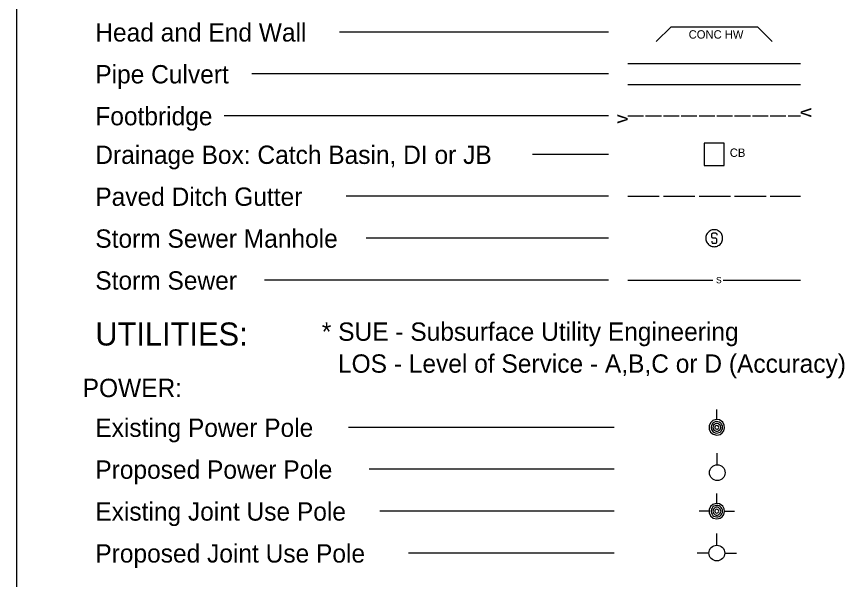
# Model space of a CAD drawing. Extents: x 754056.72 to 754059.56, y 596603.78 to 596605.61.
# Drawn here: x 754058.141 to 754058.806, y 596604.7 to 596605.152 of the extents above; entities that cross this region are included whole.
import ezdxf

# ---------------------------------------------------------------- set-up
doc = ezdxf.new("R2010")
doc.units = 0
doc.layers.add('Sheet_Symbology', color=7, linetype='Continuous')
doc.layers.add('z - Construction', color=7, linetype='Continuous')

msp = doc.modelspace()

# ---------------------------------------------------------------- linework, layer by layer
at = {"layer": 'Sheet_Symbology'}
for p, q in [((754058.65501, 596605.13174), (754058.66691, 596605.14364)), ((754058.66691, 596605.14364), (754058.73627, 596605.14364)), ((754058.73627, 596605.14364), (754058.74817, 596605.13174)), ((754058.61659, 596605.13943), (754058.40084, 596605.13943)), ((754058.63222, 596605.11421), (754058.77095, 596605.11421)), ((754058.61659, 596605.1058), (754058.3304, 596605.1058)), ((754058.63222, 596605.09739), (754058.77095, 596605.09739)), ((754058.61659, 596605.07217), (754058.30806, 596605.07217)), ((754058.63222, 596605.07217), (754058.64484, 596605.07217)), ((754058.64652, 596605.07217), (754058.65913, 596605.07217)), ((754058.66081, 596605.07217), (754058.67342, 596605.07217)), ((754058.6751, 596605.07217), (754058.68772, 596605.07217)), ((754058.6894, 596605.07217), (754058.70201, 596605.07217)), ((754058.70369, 596605.07217), (754058.7163, 596605.07217)), ((754058.71798, 596605.07217), (754058.7306, 596605.07217)), ((754058.73228, 596605.07217), (754058.74489, 596605.07217)), ((754058.74657, 596605.07217), (754058.75918, 596605.07217)), ((754058.76086, 596605.07217), (754058.77095, 596605.07217)), ((754058.61659, 596605.04117), (754058.55556, 596605.04117)), ((754058.61659, 596605.00754), (754058.40608, 596605.00754)), ((754058.63222, 596605.00754), (754058.65745, 596605.00754)), ((754058.66081, 596605.00754), (754058.68603, 596605.00754)), ((754058.6894, 596605.00754), (754058.71462, 596605.00754)), ((754058.71798, 596605.00754), (754058.74321, 596605.00754)), ((754058.74657, 596605.00754), (754058.77095, 596605.00754)), ((754058.69957, 596604.97511), (754058.69957, 596604.97691)), ((754058.70077, 596604.97811), (754058.70257, 596604.97811)), ((754058.70372, 596604.97691), (754058.70372, 596604.97631)), ((754058.61659, 596604.97391), (754058.42207, 596604.97391)), ((754058.69957, 596604.97156), (754058.69957, 596604.97096)), ((754058.70257, 596604.97396), (754058.70077, 596604.97396)), ((754058.70077, 596604.96981), (754058.70257, 596604.96981)), ((754058.70372, 596604.97096), (754058.70372, 596604.97281)), ((754058.61659, 596604.94028), (754058.34047, 596604.94028)), ((754058.63222, 596604.94028), (754058.70037, 596604.94028)), ((754058.70878, 596604.94028), (754058.77095, 596604.94028)), ((754058.70369, 596604.82827), (754058.70369, 596604.83633)), ((754058.62127, 596604.82206), (754058.40794, 596604.82206)), ((754058.70405, 596604.79198), (754058.70405, 596604.80144)), ((754058.62127, 596604.78843), (754058.42456, 596604.78843)), ((754058.70369, 596604.761), (754058.70369, 596604.76907)), ((754058.62127, 596604.75479), (754058.43309, 596604.75479)), ((754058.69748, 596604.75479), (754058.68941, 596604.75479)), ((754058.7099, 596604.75479), (754058.71797, 596604.75479)), ((754058.70369, 596604.72749), (754058.70369, 596604.73695)), ((754058.62127, 596604.72116), (754058.4561, 596604.72116)), ((754058.69738, 596604.72118), (754058.68793, 596604.72118)), ((754058.71, 596604.72118), (754058.71945, 596604.72118))]:
    msp.add_line(p, q, dxfattribs=at)
for points in [[(754058.6935, 596605.03224), (754058.70966, 596605.03224), (754058.70966, 596605.05012), (754058.6935, 596605.05012)], [(754058.70369, 596604.81585), (754058.7063, 596604.81635), (754058.70804, 596604.81759), (754058.7094, 596604.81933), (754058.7099, 596604.82168), (754058.70965, 596604.82392), (754058.70841, 596604.82615), (754058.70593, 596604.82802), (754058.70307, 596604.82827), (754058.70059, 596604.82752), (754058.6986, 596604.82578), (754058.69761, 596604.82342), (754058.69761, 596604.82069), (754058.6986, 596604.81834), (754058.70083, 596604.81647)], [(754058.70369, 596604.74859), (754058.7063, 596604.74908), (754058.70804, 596604.75033), (754058.7094, 596604.75207), (754058.7099, 596604.75442), (754058.70965, 596604.75666), (754058.70841, 596604.75889), (754058.70593, 596604.76075), (754058.70307, 596604.761), (754058.70059, 596604.76026), (754058.6986, 596604.75852), (754058.69761, 596604.75616), (754058.69761, 596604.75343), (754058.6986, 596604.75107), (754058.70083, 596604.74921)]]:
    msp.add_lwpolyline(points, close=True, dxfattribs=at)
for points in [[(754058.70159, 596604.98073), (754058.70071, 596604.98068), (754058.6999, 596604.98052), (754058.69907, 596604.98024), (754058.69831, 596604.97986), (754058.6976, 596604.97942), (754058.69695, 596604.97888), (754058.69634, 596604.97822), (754058.69585, 596604.97757), (754058.69542, 596604.9768), (754058.69514, 596604.97598), (754058.69492, 596604.97516), (754058.69482, 596604.97434), (754058.69482, 596604.97347), (754058.69492, 596604.97265), (754058.69514, 596604.97178), (754058.69542, 596604.97101), (754058.69585, 596604.97025), (754058.69634, 596604.96959), (754058.69695, 596604.96894), (754058.6976, 596604.96839), (754058.69831, 596604.96795), (754058.69907, 596604.96757), (754058.6999, 596604.9673), (754058.70077, 596604.96713), (754058.70159, 596604.96708), (754058.70246, 596604.96713), (754058.70328, 596604.9673), (754058.7041, 596604.96757), (754058.70486, 596604.96795), (754058.70557, 596604.96839), (754058.70623, 596604.96894), (754058.70683, 596604.96959), (754058.70732, 596604.97025), (754058.70776, 596604.97101), (754058.70803, 596604.97183), (754058.70825, 596604.97265), (754058.70836, 596604.97347), (754058.70836, 596604.97434), (754058.70825, 596604.97516), (754058.70803, 596604.97604), (754058.70776, 596604.9768), (754058.70732, 596604.97757), (754058.70683, 596604.97822), (754058.70623, 596604.97888), (754058.70557, 596604.97942), (754058.70486, 596604.97986), (754058.7041, 596604.98024), (754058.70328, 596604.98052), (754058.70241, 596604.98068), (754058.70159, 596604.98073)], [(754058.69957, 596604.97691), (754058.69968, 596604.97729), (754058.69984, 596604.97762), (754058.70006, 596604.97784), (754058.70039, 596604.978), (754058.70077, 596604.97811)], [(754058.70257, 596604.97811), (754058.7029, 596604.978), (754058.70323, 596604.97784), (754058.7035, 596604.97762), (754058.70366, 596604.97729), (754058.70372, 596604.97691)], [(754058.70077, 596604.97396), (754058.70039, 596604.97402), (754058.70006, 596604.97418), (754058.69984, 596604.97445), (754058.69968, 596604.97478), (754058.69957, 596604.97511)], [(754058.69957, 596604.97101), (754058.69968, 596604.97063), (754058.69984, 596604.9703), (754058.70006, 596604.97003), (754058.70039, 596604.96987), (754058.70077, 596604.96981)], [(754058.70372, 596604.97276), (754058.70366, 596604.97314), (754058.7035, 596604.97347), (754058.70323, 596604.97374), (754058.7029, 596604.97391), (754058.70257, 596604.97396)], [(754058.70257, 596604.96981), (754058.7029, 596604.96987), (754058.70323, 596604.97003), (754058.7035, 596604.9703), (754058.70366, 596604.97063), (754058.70372, 596604.97101)], [(754058.70829, 596604.82206), (754058.70816, 596604.82317), (754058.70779, 596604.82417), (754058.70717, 596604.82504), (754058.70642, 596604.82578), (754058.70555, 596604.82628), (754058.70443, 596604.82653), (754058.70344, 596604.82665), (754058.70232, 596604.8264), (754058.70133, 596604.82603), (754058.70059, 596604.82541), (754058.69985, 596604.82454), (754058.69934, 596604.82367), (754058.69909, 596604.82255), (754058.69909, 596604.82156), (754058.69934, 596604.82044), (754058.69985, 596604.81957), (754058.70059, 596604.81871), (754058.70133, 596604.81809), (754058.70232, 596604.81771), (754058.70344, 596604.81746), (754058.70443, 596604.81759), (754058.70555, 596604.81784), (754058.70642, 596604.81834), (754058.70717, 596604.81908), (754058.70779, 596604.81995), (754058.70816, 596604.82094), (754058.70829, 596604.82206)], [(754058.70679, 596604.82206), (754058.70667, 596604.82293), (754058.7063, 596604.82379), (754058.70568, 596604.82442), (754058.70493, 596604.82491), (754058.70419, 596604.82516), (754058.70319, 596604.82516), (754058.70245, 596604.82491), (754058.7017, 596604.82442), (754058.70108, 596604.82379), (754058.70071, 596604.82293), (754058.70059, 596604.82206), (754058.70071, 596604.82119), (754058.70108, 596604.82032), (754058.7017, 596604.8197), (754058.70245, 596604.8192), (754058.70319, 596604.81896), (754058.70419, 596604.81896), (754058.70493, 596604.8192), (754058.70568, 596604.8197), (754058.7063, 596604.82032), (754058.70667, 596604.82119), (754058.70679, 596604.82206)], [(754058.70518, 596604.82206), (754058.70506, 596604.82268), (754058.70468, 596604.82317), (754058.70419, 596604.82342), (754058.70357, 596604.82355), (754058.70295, 596604.8233), (754058.70245, 596604.82293), (754058.7022, 596604.82231), (754058.7022, 596604.82181), (754058.70245, 596604.82119), (754058.70295, 596604.82081), (754058.70357, 596604.82057), (754058.70419, 596604.82069), (754058.70468, 596604.82094), (754058.70506, 596604.82144), (754058.70518, 596604.82206)], [(754058.70829, 596604.75479), (754058.70816, 596604.75591), (754058.70779, 596604.7569), (754058.70717, 596604.75777), (754058.70642, 596604.75852), (754058.70555, 596604.75902), (754058.70443, 596604.75926), (754058.70344, 596604.75939), (754058.70232, 596604.75914), (754058.70133, 596604.75877), (754058.70059, 596604.75815), (754058.69985, 596604.75728), (754058.69934, 596604.75641), (754058.69909, 596604.75529), (754058.69909, 596604.7543), (754058.69934, 596604.75318), (754058.69985, 596604.75231), (754058.70059, 596604.75144), (754058.70133, 596604.75082), (754058.70232, 596604.75045), (754058.70344, 596604.7502), (754058.70443, 596604.75033), (754058.70555, 596604.75057), (754058.70642, 596604.75107), (754058.70717, 596604.75182), (754058.70779, 596604.75269), (754058.70816, 596604.75368), (754058.70829, 596604.75479)], [(754058.70679, 596604.75479), (754058.70667, 596604.75566), (754058.7063, 596604.75653), (754058.70568, 596604.75715), (754058.70493, 596604.75765), (754058.70419, 596604.7579), (754058.70319, 596604.7579), (754058.70245, 596604.75765), (754058.7017, 596604.75715), (754058.70108, 596604.75653), (754058.70071, 596604.75566), (754058.70059, 596604.75479), (754058.70071, 596604.75393), (754058.70108, 596604.75306), (754058.7017, 596604.75244), (754058.70245, 596604.75194), (754058.70319, 596604.75169), (754058.70419, 596604.75169), (754058.70493, 596604.75194), (754058.70568, 596604.75244), (754058.7063, 596604.75306), (754058.70667, 596604.75393), (754058.70679, 596604.75479)], [(754058.70518, 596604.75479), (754058.70506, 596604.75541), (754058.70468, 596604.75591), (754058.70419, 596604.75616), (754058.70357, 596604.75628), (754058.70295, 596604.75604), (754058.70245, 596604.75566), (754058.7022, 596604.75505), (754058.7022, 596604.75454), (754058.70245, 596604.75393), (754058.70295, 596604.75355), (754058.70357, 596604.75331), (754058.70419, 596604.75343), (754058.70468, 596604.75368), (754058.70506, 596604.75418), (754058.70518, 596604.75479)]]:
    msp.add_lwpolyline(points, dxfattribs=at)
for centre in [(754058.70405, 596604.78567), (754058.70369, 596604.72116)]:
    msp.add_circle(centre, 0.00631, dxfattribs=at)
at = {"layer": 'z - Construction'}
msp.add_line((754058.1415, 596605.54909), (754058.14146, 596603.84076), dxfattribs=at)

# ---------------------------------------------------------------- texts
at = {"layer": 'Sheet_Symbology'}
for s, height, p in [('Head and End Wall', 0.0147137, (754058.20467, 596605.13178)), ('CONC HW', 0.006726, (754058.68107, 596605.13412)), ('Pipe Culvert', 0.0147137, (754058.20467, 596605.09817)), ('Footbridge', 0.014714, (754058.20469, 596605.06454)), ('Drainage Box: Catch Basin, DI or JB', 0.0147137, (754058.20469, 596605.03354)), ('CB', 0.006726, (754058.71409, 596605.03919)), ('Paved Ditch Gutter', 0.0147137, (754058.20469, 596604.99989)), ('Storm Sewer Manhole', 0.0147137, (754058.20469, 596604.96626)), ('Storm Sewer', 0.0147137, (754058.20469, 596604.93262)), ('S', 0.00504, (754058.70306, 596604.93775)), ('UTILITIES:', 0.018497, (754058.20467, 596604.88776)), ('* SUE - Subsurface Utility Engineering', 0.0147137, (754058.38654, 596604.89155)), ('LOS - Level of Service - A,B,C or D (Accuracy) ', 0.0147137, (754058.39951, 596604.86593)), ('POWER:', 0.014714, (754058.19453, 596604.84638)), ('Existing Power Pole', 0.0147137, (754058.20469, 596604.81443)), ('Proposed Power Pole', 0.0147137, (754058.20469, 596604.7808)), ('Existing Joint Use Pole', 0.0147137, (754058.20469, 596604.74719)), ('Proposed Joint Use Pole', 0.0147137, (754058.20471, 596604.71353))]:
    msp.add_text(s, height=height, dxfattribs=at).set_placement(p)
for rotation, p in [(270.24085, (754058.77093, 596605.07846)), (89.75915, (754058.6322, 596605.06589))]:
    msp.add_text('v', height=0.0111, rotation=rotation, dxfattribs=at).set_placement(p)

doc.saveas('drawing.dxf')
